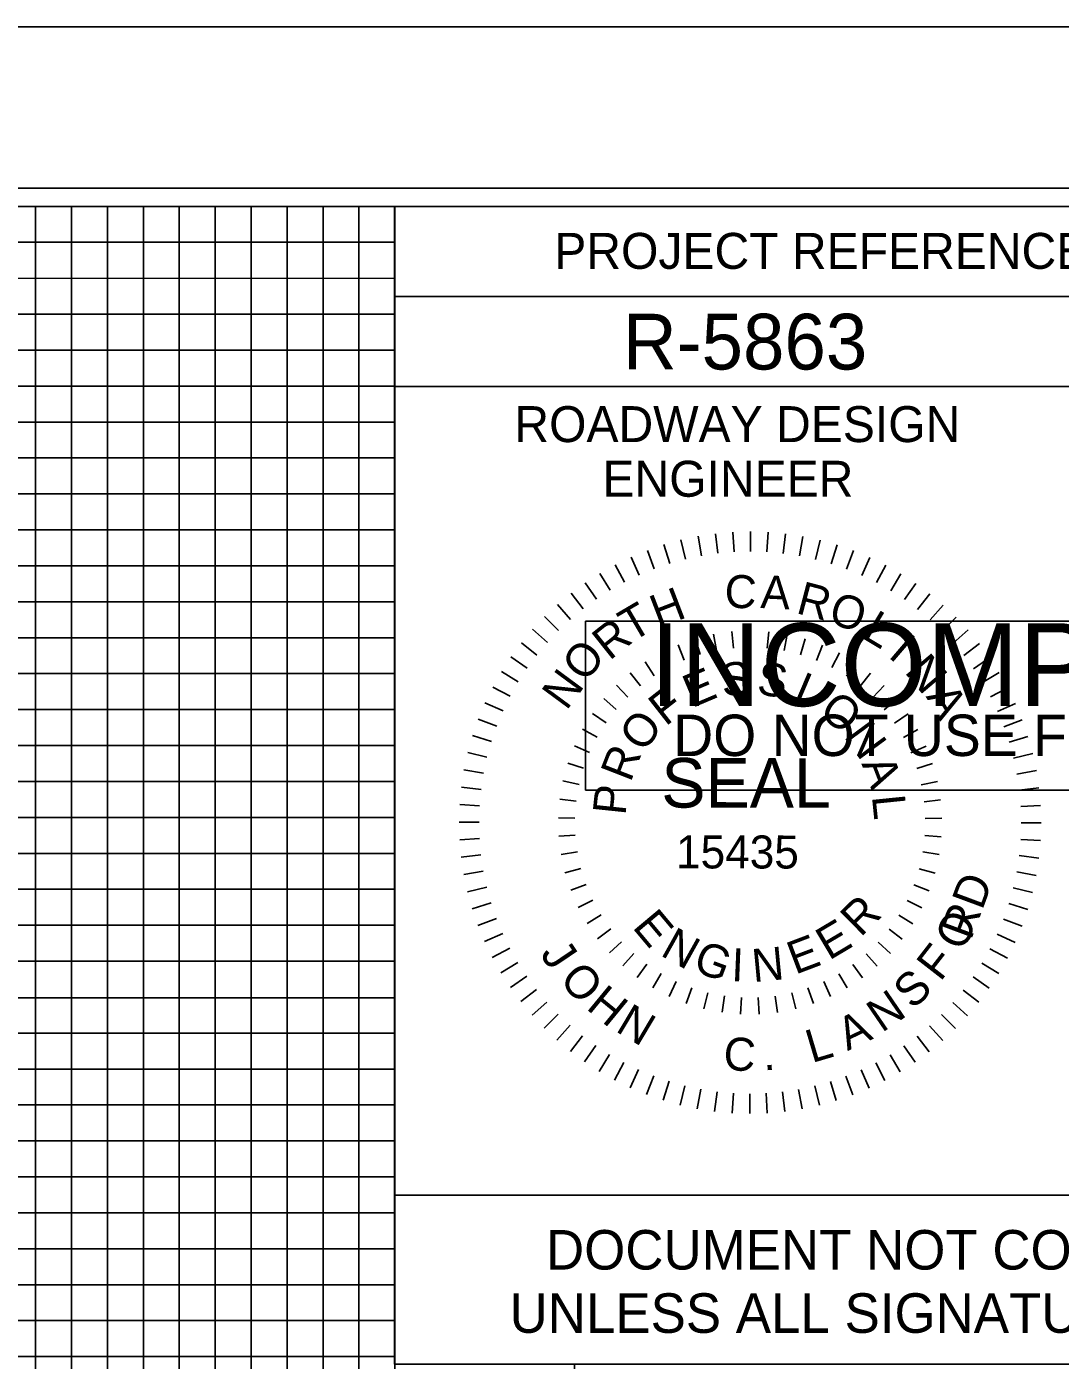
# Model space of a CAD drawing. Extents: x 557032 to 558716, y 513430 to 514605.
# Drawn here: x 558448.2 to 558592, y 514344.9 to 514530.4 of the extents above; entities that cross this region are included whole.
import ezdxf

# ---------------------------------------------------------------- set-up
doc = ezdxf.new("R2010")
doc.units = 0
for name, color, linetype in [('Old_Level_21', 7, 'Continuous'), ('Scratch_Level_5', 7, 'Continuous'), ('Sheet Cutting Line CELL', 7, 'Continuous'), ('Sheet Data Field CELL', 7, 'Continuous'), ('Sheet DOT Grid CELL', 7, 'Continuous'), ('Sheet Plot Border Inside CELL', 7, 'Continuous'), ('Sheet Plot Border Outside CELL', 7, 'Continuous'), ('Sheet Profile CELL', 7, 'Continuous'), ('Sheet Profile Grid Major CELL', 7, 'Continuous'), ('Sheet Profile Grid Middle CELL', 7, 'Continuous'), ('Sheet Profile Grid Minor CELL', 7, 'Continuous'), ('Sheet Sticker Exception Certification CELL', 7, 'Continuous'), ('Sheet Sticker Incomplete CELL', 7, 'Continuous')]:
    doc.layers.add(name, color=color, linetype=linetype)

msp = doc.modelspace()

# ---------------------------------------------------------------- linework, layer by layer
at = {"layer": 'Old_Level_21'}
for p, q in [((558539.24, 514459), (558539.89, 514456.32)), ((558541.63, 514459.51), (558542.12, 514456.8)), ((558544.04, 514459.87), (558544.37, 514457.14)), ((558546.48, 514460.09), (558546.64, 514457.34)), ((558548.92, 514460.16), (558548.92, 514457.4)), ((558551.37, 514460.08), (558551.2, 514457.33)), ((558553.8, 514459.86), (558553.47, 514457.12)), ((558556.22, 514459.49), (558555.72, 514456.78)), ((558558.61, 514458.97), (558557.95, 514456.3)), ((558534.57, 514457.55), (558535.54, 514454.97)), ((558536.88, 514458.35), (558537.69, 514455.71)), ((558560.97, 514458.32), (558560.14, 514455.68)), ((558563.27, 514457.51), (558562.29, 514454.93)), ((558530.11, 514455.55), (558531.38, 514453.11)), ((558532.31, 514456.62), (558533.43, 514454.1)), ((558565.53, 514456.57), (558564.4, 514454.06)), ((558567.73, 514455.5), (558566.44, 514453.06)), ((558527.97, 514454.35), (558529.4, 514451.99)), ((558569.86, 514454.3), (558568.43, 514451.94)), ((558523.95, 514451.58), (558525.65, 514449.41)), ((558525.92, 514453.03), (558527.48, 514450.76)), ((558571.91, 514452.96), (558570.34, 514450.7)), ((558522.07, 514450.02), (558523.89, 514447.95)), ((558573.87, 514451.51), (558572.17, 514449.34)), ((558575.75, 514449.94), (558573.92, 514447.88)), ((558520.28, 514448.35), (558522.23, 514446.39)), ((558577.53, 514448.27), (558575.58, 514446.32)), ((558518.61, 514446.57), (558520.67, 514444.74)), ((558546.33, 514446.24), (558546.55, 514443.95)), ((558548.9, 514446.36), (558548.9, 514444.06)), ((558548.9, 514444.06), (558548.9, 514446.36)), ((558551.48, 514446.23), (558551.26, 514443.95)), ((558579.2, 514446.48), (558577.14, 514444.66)), ((558517.04, 514444.69), (558519.21, 514442.99)), ((558538.84, 514444.41), (558539.7, 514442.28)), ((558541.28, 514445.26), (558541.93, 514443.05)), ((558543.78, 514445.87), (558544.21, 514443.61)), ((558554.03, 514445.86), (558553.59, 514443.6)), ((558556.53, 514445.24), (558555.87, 514443.03)), ((558558.96, 514444.38), (558558.09, 514442.25)), ((558580.77, 514444.6), (558578.59, 514442.91)), ((558515.59, 514442.73), (558517.85, 514441.15)), ((558536.5, 514443.32), (558537.56, 514441.29)), ((558561.3, 514443.29), (558560.23, 514441.26)), ((558582.21, 514442.63), (558579.94, 514441.07)), ((558514.26, 514440.68), (558516.61, 514439.24)), ((558532.19, 514440.51), (558533.63, 514438.71)), ((558534.28, 514442.02), (558535.53, 514440.09)), ((558563.52, 514441.98), (558562.26, 514440.06)), ((558565.6, 514440.46), (558564.16, 514438.67)), ((558583.54, 514440.58), (558581.18, 514439.15)), ((558530.26, 514438.8), (558531.86, 514437.15)), ((558567.53, 514438.75), (558565.92, 514437.1)), ((558513.05, 514438.54), (558515.49, 514437.26)), ((558528.5, 514436.92), (558530.25, 514435.43)), ((558569.28, 514436.86), (558567.52, 514435.38)), ((558584.74, 514438.44), (558582.29, 514437.17)), ((558511.98, 514436.35), (558514.49, 514435.21)), ((558526.93, 514434.87), (558528.82, 514433.56)), ((558585.8, 514436.24), (558583.29, 514435.12)), ((558511.04, 514434.09), (558513.62, 514433.11)), ((558570.85, 514434.81), (558568.95, 514433.5)), ((558586.74, 514433.98), (558584.15, 514433.01)), ((558510.24, 514431.78), (558512.87, 514430.96)), ((558525.57, 514432.68), (558527.58, 514431.56)), ((558572.2, 514432.62), (558570.19, 514431.5)), ((558587.53, 514431.67), (558584.89, 514430.86)), ((558509.58, 514429.42), (558512.25, 514428.76)), ((558524.42, 514430.37), (558526.53, 514429.45)), ((558573.34, 514430.3), (558571.23, 514429.39)), ((558588.19, 514429.31), (558585.51, 514428.66)), ((558523.51, 514427.96), (558525.69, 514427.25)), ((558574.25, 514427.89), (558572.06, 514427.19)), ((558509.06, 514427.04), (558511.77, 514426.54)), ((558588.7, 514426.92), (558585.98, 514426.43)), ((558508.69, 514424.62), (558511.43, 514424.28)), ((558522.82, 514425.48), (558525.07, 514424.98)), ((558574.93, 514425.4), (558572.68, 514424.91)), ((558589.06, 514424.51), (558586.32, 514424.18)), ((558508.47, 514422.19), (558511.22, 514422.02)), ((558522.39, 514422.94), (558524.67, 514422.66)), ((558575.36, 514422.86), (558573.08, 514422.59)), ((558589.28, 514422.07), (558586.52, 514421.91)), ((558522.2, 514420.36), (558524.49, 514420.3)), ((558575.54, 514420.29), (558573.24, 514420.24)), ((558508.39, 514419.74), (558511.15, 514419.74)), ((558589.35, 514419.63), (558586.59, 514419.63)), ((558508.46, 514417.29), (558511.21, 514417.46)), ((558522.25, 514417.79), (558524.55, 514417.95)), ((558575.47, 514417.71), (558573.18, 514417.88)), ((558589.27, 514417.18), (558586.52, 514417.35)), ((558508.68, 514414.86), (558511.41, 514415.19)), ((558522.57, 514415.23), (558524.83, 514415.61)), ((558572.91, 514415.63), (558575.17, 514415.24)), ((558589.04, 514414.75), (558586.31, 514415.08)), ((558509.04, 514412.44), (558511.75, 514412.93)), ((558523.11, 514412.71), (558525.33, 514413.31)), ((558574.6, 514412.64), (558572.38, 514413.24)), ((558588.67, 514412.33), (558585.96, 514412.83)), ((558523.91, 514410.26), (558526.06, 514411.07)), ((558573.8, 514410.19), (558571.65, 514411)), ((558509.55, 514410.05), (558512.23, 514410.7)), ((558524.94, 514407.89), (558527, 514408.91)), ((558588.16, 514409.94), (558585.48, 514410.6)), ((558510.2, 514407.69), (558512.84, 514408.51)), ((558572.76, 514407.83), (558570.71, 514408.85)), ((558587.5, 514407.58), (558584.86, 514408.41)), ((558511, 514405.38), (558513.58, 514406.36)), ((558526.18, 514405.64), (558528.14, 514406.85)), ((558571.51, 514405.58), (558569.56, 514406.79)), ((558586.7, 514405.28), (558584.12, 514406.26)), ((558511.93, 514403.12), (558514.45, 514404.25)), ((558527.64, 514403.51), (558529.48, 514404.91)), ((558570.04, 514403.45), (558568.22, 514404.85)), ((558585.75, 514403.02), (558583.24, 514404.15)), ((558513, 514400.92), (558515.44, 514402.2)), ((558529.31, 514401.54), (558530.99, 514403.1)), ((558531.15, 514399.74), (558532.68, 514401.46)), ((558568.38, 514401.49), (558566.7, 514403.05)), ((558584.69, 514400.82), (558582.24, 514402.11)), ((558514.2, 514398.79), (558516.56, 514400.22)), ((558533.16, 514398.12), (558534.51, 514399.98)), ((558564.52, 514398.08), (558563.17, 514399.94)), ((558566.53, 514399.69), (558565.01, 514401.41)), ((558583.48, 514398.69), (558581.12, 514400.13)), ((558515.52, 514396.73), (558517.79, 514398.3)), ((558535.31, 514396.71), (558536.48, 514398.69)), ((558562.36, 514396.67), (558561.2, 514398.65)), ((558582.15, 514396.64), (558579.88, 514398.21)), ((558516.97, 514394.77), (558519.14, 514396.46)), ((558537.59, 514395.51), (558538.56, 514397.59)), ((558539.98, 514394.53), (558540.75, 514396.7)), ((558542.99, 514396.02), (558542.43, 514393.79)), ((558555.22, 514393.77), (558554.67, 514396.01)), ((558557.68, 514394.5), (558556.92, 514396.68)), ((558560.07, 514395.47), (558559.11, 514397.56)), ((558580.7, 514394.68), (558578.53, 514396.38)), ((558518.53, 514392.88), (558520.6, 514394.71)), ((558544.98, 514393.29), (558545.31, 514395.56)), ((558547.54, 514393.04), (558547.65, 514395.33)), ((558550.12, 514393.03), (558550.01, 514395.33)), ((558552.68, 514393.28), (558552.36, 514395.55)), ((558579.13, 514392.8), (558577.07, 514394.63)), ((558520.21, 514391.1), (558522.16, 514393.05)), ((558577.45, 514391.02), (558575.5, 514392.97)), ((558521.98, 514389.42), (558523.81, 514391.48)), ((558575.67, 514389.35), (558573.84, 514391.41)), ((558523.86, 514387.85), (558525.56, 514390.02)), ((558525.83, 514386.4), (558527.4, 514388.67)), ((558571.82, 514386.34), (558570.25, 514388.61)), ((558573.79, 514387.78), (558572.09, 514389.96)), ((558527.88, 514385.07), (558529.31, 514387.43)), ((558569.76, 514385.01), (558568.34, 514387.37)), ((558530.01, 514383.87), (558531.29, 514386.31)), ((558532.2, 514382.8), (558533.34, 514385.31)), ((558565.43, 514382.75), (558564.3, 514385.27)), ((558567.63, 514383.81), (558566.35, 514386.26)), ((558534.46, 514381.85), (558535.45, 514384.43)), ((558536.77, 514381.05), (558537.59, 514383.69)), ((558539.13, 514380.39), (558539.79, 514383.07)), ((558558.5, 514380.37), (558557.85, 514383.05)), ((558560.86, 514381.02), (558560.04, 514383.66)), ((558563.17, 514381.81), (558562.19, 514384.4)), ((558541.52, 514379.88), (558542.02, 514382.59)), ((558543.93, 514379.51), (558544.27, 514382.24)), ((558546.37, 514379.28), (558546.54, 514382.04)), ((558548.81, 514379.2), (558548.81, 514381.96)), ((558551.26, 514379.28), (558551.1, 514382.03)), ((558553.69, 514379.49), (558553.36, 514382.23)), ((558556.11, 514379.86), (558555.62, 514382.57))]:
    msp.add_line(p, q, dxfattribs=at)
at = {"layer": 'Scratch_Level_5'}
msp.add_lwpolyline([(557207.08, 514505.4), (557207.08, 513980.4), (558649.45, 513980.4), (558649.45, 514344.35), (558499.4, 514344.35), (558499.4, 514505.4)], close=True, dxfattribs=at)
at = {"layer": 'Sheet Cutting Line CELL'}
msp.add_line((558716.45, 514530.4), (557032.45, 514530.4), dxfattribs=at)
at = {"layer": 'Sheet DOT Grid CELL'}
for p, q in [((558449.45, 514005.4), (558449.45, 514505.4)), ((558449.45, 514036.11), (558449.45, 514488.82)), ((558499.4, 514455.4), (557199.45, 514455.4)), ((558484.51, 514455.4), (557203.74, 514455.4)), ((558499.4, 514405.4), (557199.45, 514405.4)), ((558484.51, 514405.4), (557203.83, 514405.4)), ((558499.45, 514005.4), (558499.45, 514367.85)), ((558499.45, 514355.4), (557199.45, 514355.4)), ((558484.51, 514355.4), (557203.92, 514355.4))]:
    msp.add_line(p, q, dxfattribs=at)
at = {"layer": 'Sheet Plot Border Inside CELL'}
msp.add_lwpolyline([(557045.45, 513452.85), (558711.95, 513452.85), (558711.95, 514507.95), (557045.45, 514507.95)], close=True, dxfattribs=at)
at = {"layer": 'Sheet Plot Border Outside CELL'}
msp.add_lwpolyline([(557032.45, 513430.4), (558716.45, 513430.4), (558716.45, 514530.4), (557032.45, 514530.4)], close=True, dxfattribs=at)
at = {"layer": 'Sheet Profile CELL'}
msp.add_line((558499.4, 514492.85), (558699.45, 514492.85), dxfattribs=at)
for points in [[(558699.45, 514505.4), (557199.45, 514505.4), (557199.45, 513455.4), (558699.45, 513455.4)], [(558499.4, 514505.4), (558699.45, 514505.4), (558699.45, 514480.35), (558499.4, 514480.35)], [(558499.4, 514480.35), (558599.45, 514480.35), (558599.45, 514367.85), (558499.4, 514367.85)]]:
    msp.add_lwpolyline(points, close=True, dxfattribs=at)
at = {"layer": 'Sheet Profile Grid Major CELL'}
for points in [[(557949.45, 514005.4), (557999.45, 514005.4), (557999.45, 514505.4), (558049.45, 514505.4), (558049.45, 514005.4), (558099.45, 514005.4), (558099.45, 514505.4), (558149.45, 514505.4), (558149.45, 514005.4), (558199.45, 514005.4), (558199.45, 514505.4), (558249.45, 514505.4), (558249.45, 514005.4), (558299.45, 514005.4), (558299.45, 514505.4), (558349.45, 514505.4), (558349.45, 514005.4), (558399.45, 514005.4), (558399.45, 514505.4), (558449.45, 514505.4), (558449.45, 514005.4), (558499.45, 514005.4), (558499.45, 514505.4), (558525.75, 514505.4)], [(558449.45, 514488.82), (558449.45, 514036.11)], [(557199.45, 514455.4), (558499.45, 514455.4)], [(557203.74, 514455.4), (558484.51, 514455.4)], [(558499.45, 514405.4), (557199.45, 514405.4), (557199.45, 514355.4), (558499.45, 514355.4)], [(558484.51, 514405.4), (557203.83, 514405.4)], [(557203.92, 514355.4), (558484.51, 514355.4)]]:
    msp.add_lwpolyline(points, dxfattribs=at)
at = {"layer": 'Sheet Profile Grid Middle CELL'}
for p, q in [((557199.45, 514480.4), (558499.4, 514480.4)), ((557203.7, 514480.4), (558484.51, 514480.4))]:
    msp.add_line(p, q, dxfattribs=at)
for points in [[(558424.45, 514505.4), (558474.45, 514505.4), (558474.45, 514005.4), (558524.45, 514005.4), (558524.45, 514344.35)], [(558474.45, 514488.82), (558474.45, 514036.62)], [(558499.45, 514430.4), (557199.45, 514430.4), (557199.45, 514380.4), (558499.45, 514380.4)], [(558484.51, 514430.4), (557203.79, 514430.4)], [(557203.88, 514380.4), (558484.51, 514380.4)]]:
    msp.add_lwpolyline(points, dxfattribs=at)
at = {"layer": 'Sheet Profile Grid Minor CELL'}
for p, q in [((557249.45, 514500.4), (558499.45, 514500.4)), ((558499.45, 514495.4), (557249.45, 514495.05)), ((557249.45, 514490.4), (558499.45, 514490.4)), ((558499.4, 514370.4), (557249.45, 514370.4)), ((558484.51, 514370.4), (557249.45, 514370.4)), ((558499.45, 514365.4), (557249.45, 514365.4)), ((558484.51, 514365.4), (557249.45, 514365.4)), ((558499.45, 514360.4), (557249.45, 514360.4)), ((558484.51, 514360.4), (557249.45, 514360.4)), ((557249.45, 514350.4), (558499.45, 514350.4)), ((557249.45, 514350.4), (558484.51, 514350.4)), ((558499.45, 514345.4), (557249.45, 514345.4)), ((558484.51, 514345.4), (557249.45, 514345.4))]:
    msp.add_line(p, q, dxfattribs=at)
for points in [[(558444.45, 514505.4), (558454.45, 514505.4), (558454.45, 514005.4), (558459.45, 514005.4), (558459.45, 514505.4), (558464.45, 514505.4), (558464.45, 514005.4), (558469.45, 514005.4), (558469.45, 514505.4), (558479.45, 514505.4), (558479.45, 514005.4), (558484.45, 514005.4), (558484.45, 514505.4), (558489.45, 514505.4), (558489.45, 514005.4), (558494.45, 514005.4), (558494.45, 514505.4), (558504.45, 514505.4)], [(558454.45, 514488.82), (558454.45, 514036.21)], [(558459.45, 514036.31), (558459.45, 514488.82)], [(558464.45, 514488.82), (558464.45, 514036.42)], [(558469.45, 514036.52), (558469.45, 514488.82)], [(558479.45, 514488.82), (558479.45, 514036.72)], [(558484.45, 514036.82), (558484.45, 514488.82)], [(558499.45, 514485.4), (557249.45, 514485.4), (557249.45, 514475.4), (558499.45, 514475.4)], [(558484.51, 514485.4), (557249.45, 514485.4), (557249.45, 514475.4), (558484.51, 514475.4)], [(558499.4, 514470.4), (557249.45, 514470.4), (557249.45, 514465.4), (558499.45, 514465.4)], [(558484.51, 514470.4), (557249.45, 514470.4), (557249.45, 514465.4), (558484.51, 514465.4)], [(558499.45, 514460.4), (557249.45, 514460.4), (557249.45, 514450.4), (558499.45, 514450.4)], [(558484.51, 514460.4), (557249.45, 514460.4), (557249.45, 514450.4), (558484.51, 514450.4)], [(558499.45, 514445.4), (557249.45, 514445.4), (557249.45, 514440.4), (558499.45, 514440.4)], [(558484.51, 514445.4), (557249.45, 514445.4), (557249.45, 514440.4), (558484.51, 514440.4)], [(558499.45, 514435.4), (557249.45, 514435.4), (557249.45, 514425.4), (558499.45, 514425.4)], [(558484.51, 514435.4), (557249.45, 514435.4), (557249.45, 514425.4), (558484.51, 514425.4)], [(558499.45, 514420.4), (557249.45, 514420.4), (557249.45, 514415.4), (558499.45, 514415.4)], [(558484.51, 514420.4), (557249.45, 514420.4), (557249.45, 514415.4), (558484.51, 514415.4)], [(558499.45, 514410.4), (557249.45, 514410.4), (557249.45, 514400.4), (558499.45, 514400.4)], [(558484.51, 514410.4), (557249.45, 514410.4), (557249.45, 514400.4), (558484.51, 514400.4)], [(558499.45, 514395.3), (557249.55, 514395.3), (557249.55, 514390.4), (558499.45, 514390.4)], [(558484.51, 514395.3), (557249.55, 514395.3), (557249.55, 514390.4), (558484.51, 514390.4)], [(558499.45, 514385.4), (557249.45, 514385.4), (557249.45, 514375.4), (558499.45, 514375.4)], [(558484.51, 514385.4), (557249.45, 514385.4), (557249.45, 514375.4), (558484.51, 514375.4)]]:
    msp.add_lwpolyline(points, dxfattribs=at)
at = {"layer": 'Sheet Sticker Exception Certification CELL'}
for p, q in [((558499.4, 514344.35), (558499.4, 514367.85)), ((558499.4, 514367.85), (558699.44, 514367.85)), ((558499.4, 514344.35), (558499.4, 514367.85)), ((558499.4, 514367.85), (558699.44, 514367.85))]:
    msp.add_line(p, q, dxfattribs=at)
at = {"layer": 'Sheet Sticker Incomplete CELL'}
msp.add_lwpolyline([(558525.97, 514424.19), (558525.97, 514447.69), (558672.97, 514447.69), (558672.97, 514424.19)], close=True, dxfattribs=at)

# ---------------------------------------------------------------- texts
at = {"layer": 'Old_Level_21'}
for s, height, rotation, p in [('C', 4.59, 357.2771, (558545.23, 514449.63)), ('A', 4.59, 357.2771, (558550.25, 514449.53)), ('H', 4.59, 20.9878, (558536.08, 514446.69)), ('R', 4.59, 345.2678, (558555.12, 514448.85)), ('T', 4.59, 30.4198, (558532.38, 514444.7)), ('O', 4.59, 342.211, (558559.57, 514447.52)), ('L', 4.59, 329.0747, (558564.24, 514445.47)), ('R', 4.59, 38.5807, (558529.29, 514442.13)), ('O', 4.59, 51.6375, (558525.96, 514439.04)), ('I', 4.59, 319.4993, (558567.94, 514442.8)), ('N', 4.59, 310.2048, (558570.24, 514440.63)), ('N', 4.59, 53.5969, (558523.31, 514435.16)), ('E', 4.59, 22.8645, (558540.78, 514435.59)), ('S', 4.59, 7.5683, (558545.1, 514437.16)), ('S', 4.59, 352.272, (558549.69, 514437.54)), ('I', 4.59, 336.9758, (558554.57, 514436.54)), ('F', 4.59, 38.1608, (558537.1, 514432.99)), ('O', 4.59, 321.6795, (558558.28, 514434.74)), ('A', 4.59, 300.4373, (558573.27, 514437.23)), ('O', 4.59, 53.457, (558534.04, 514429.29)), ('N', 4.59, 306.3833, (558561.81, 514431.66)), ('R', 4.59, 68.7533, (558532.22, 514425.17)), ('SEAL', 6.898, 359.9202, (558536.51, 514421.77)), ('A', 4.59, 291.0871, (558564.33, 514427.89)), ('P', 4.59, 84.0495, (558531.52, 514420.61)), ('L', 4.59, 275.7908, (558565.81, 514423.34)), ('15435', 4.595, 359.9202, (558538.56, 514413.31)), (' RD', 4.595, 69.5926, (558579, 514401.62)), ('R', 4.59, 44.4851, (558564.24, 514403.65)), ('E', 4.59, 309.9903, (558532.38, 514405.11)), ('O ', 4.595, 60.9198, (558578.33, 514401.6)), ('E', 4.59, 30.714, (558559.85, 514400.45)), ('N', 4.59, 330.8453, (558536.23, 514401.28)), ('E', 4.59, 20.7281, (558555.14, 514398.5)), ('J', 4.59, 303.8552, (558519.56, 514401.38)), ('G', 4.59, 339.6116, (558540.73, 514399.12)), ('I', 4.59, 357.7064, (558546.2, 514397.64)), ('N', 4.59, 5.336, (558549.32, 514397.48)), ('F', 4.59, 52.1272, (558575.33, 514397.45)), ('O', 4.59, 311.927, (558522.18, 514397.71)), ('S', 4.59, 43.2446, (558571.5, 514393.56)), ('H', 4.59, 320.5697, (558525.92, 514393.84)), ('N', 4.59, 34.362, (558567.19, 514390.38)), ('N', 4.59, 329.2423, (558529.99, 514390.73)), ('A', 4.59, 25.5393, (558562.42, 514387.88)), ('L', 4.59, 16.5368, (558557.45, 514386.21)), ('C', 4.59, 356.0101, (558545.05, 514385.33)), ('.', 4.59, 3.7525, (558550.76, 514385.2))]:
    msp.add_text(s, height=height, rotation=rotation, dxfattribs=at).set_placement(p)
at = {"layer": 'Sheet Data Field CELL'}
msp.add_text('R-5863   ', height=7.75, dxfattribs=at).set_placement((558531.18, 514482.71))
at = {"layer": 'Sheet Profile CELL'}
for s, height, p in [('PROJECT REFERENCE NO.', 5.0001, (558521.62, 514496.71)), ('ROADWAY DESIGN', 5.0001, (558516.07, 514472.61)), ('ENGINEER', 5, (558528.32, 514465.01))]:
    msp.add_text(s, height=height, dxfattribs=at).set_placement(p)
at = {"layer": 'Sheet Sticker Exception Certification CELL'}
for s, p in [('DOCUMENT NOT CONSIDERED FINAL', (558520.47, 514357.5)), ('DOCUMENT NOT CONSIDERED FINAL', (558520.47, 514357.5)), ('UNLESS ALL SIGNATURES COMPLETED', (558515.4, 514348.7)), ('UNLESS ALL SIGNATURES COMPLETED', (558515.4, 514348.7))]:
    msp.add_text(s, height=5.5, dxfattribs=at).set_placement(p)
at = {"layer": 'Sheet Sticker Incomplete CELL'}
for s, height, p in [('INCOMPLETE PLANS', 11.52, (558534.92, 514435.89)), ('DO NOT USE FOR R/W ACQUISITION', 5.76, (558538.17, 514428.94))]:
    msp.add_text(s, height=height, dxfattribs=at).set_placement(p)

doc.saveas('drawing.dxf')
